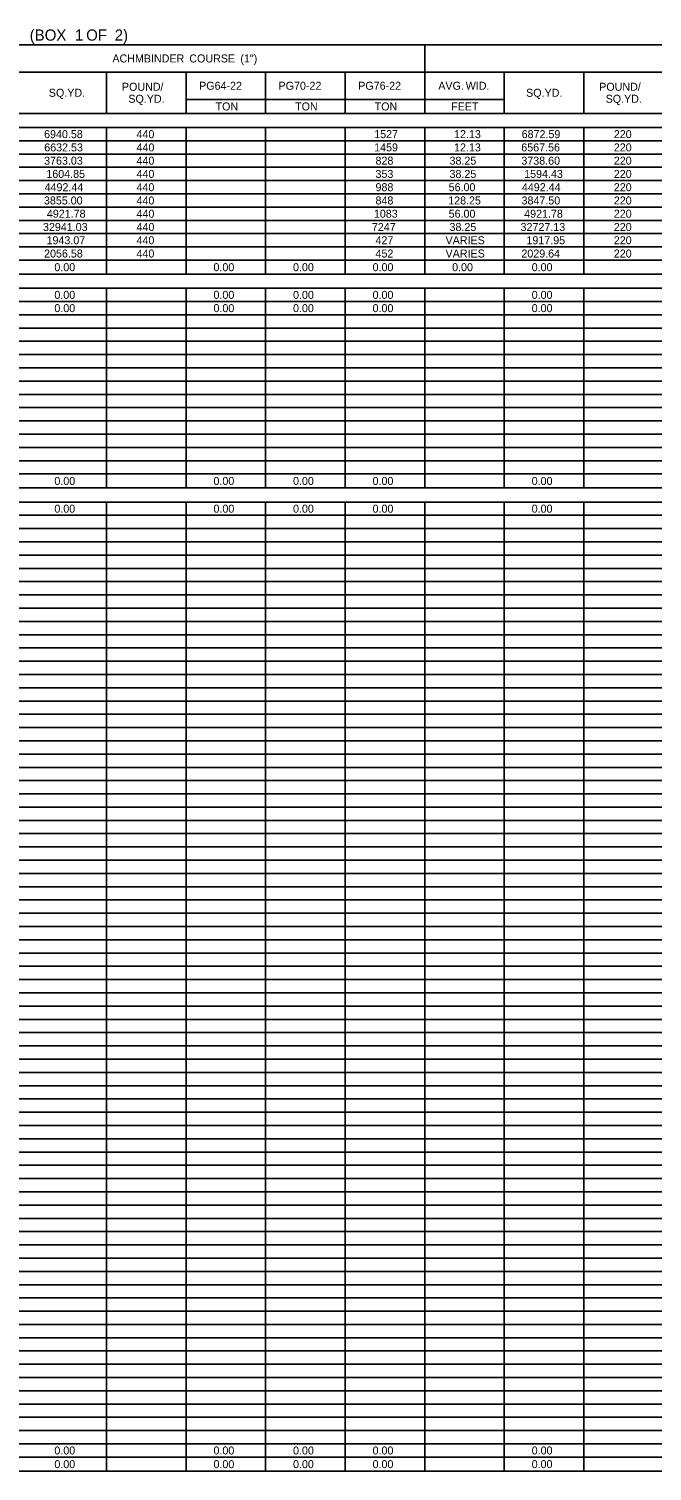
# Model space of a CAD drawing. Extents: x 1226590 to 1228573, y 151304 to 154224.
# Drawn here: x 1227629 to 1228019, y 153323 to 154224 of the extents above; entities that cross this region are included whole.
import ezdxf

# ---------------------------------------------------------------- set-up
doc = ezdxf.new("R2010")
doc.units = 0
doc.layers.add('R_Dimension', color=7, linetype='Continuous')

msp = doc.modelspace()

# ---------------------------------------------------------------- linework, layer by layer
at = {"layer": 'R_Dimension'}
for p, q in [((1226590.27, 154214.43), (1228572.93, 154214.43)), ((1227876.78, 154171.53), (1227876.78, 154214.43)), ((1226981.73, 154197.37), (1228572.93, 154197.37)), ((1227677.88, 154171.53), (1227677.88, 154197.37)), ((1227727.61, 154171.53), (1227727.61, 154197.37)), ((1227777.33, 154171.53), (1227777.33, 154197.37)), ((1227827.06, 154171.53), (1227827.06, 154197.37)), ((1227926.51, 154171.53), (1227926.51, 154197.37)), ((1227976.23, 154171.53), (1227976.23, 154197.37)), ((1227727.61, 154180.3), (1227926.51, 154180.3)), ((1226590.27, 154171.53), (1228572.93, 154171.53)), ((1227628.16, 154171.53), (1227926.51, 154171.53)), ((1227926.51, 154171.53), (1228224.86, 154171.53)), ((1226590.27, 154162.75), (1228572.93, 154162.75)), ((1226590.27, 154154.47), (1228572.93, 154154.47)), ((1227677.88, 154071.1), (1227677.88, 154162.75)), ((1227727.61, 154071.1), (1227727.61, 154162.75)), ((1227777.33, 154071.1), (1227777.33, 154162.75)), ((1227827.06, 154071.1), (1227827.06, 154162.75)), ((1227876.78, 154071.1), (1227876.78, 154162.75)), ((1227926.51, 154071.1), (1227926.51, 154162.75)), ((1227976.23, 154071.1), (1227976.23, 154162.75)), ((1226590.27, 154146.18), (1228572.93, 154146.18)), ((1226590.27, 154137.89), (1228572.93, 154137.89)), ((1226590.27, 154129.6), (1228572.93, 154129.6)), ((1226590.27, 154121.32), (1228572.93, 154121.32)), ((1226590.27, 154113.03), (1228572.93, 154113.03)), ((1226590.27, 154104.74), (1228572.93, 154104.74)), ((1226590.27, 154096.45), (1228572.93, 154096.45)), ((1226590.27, 154088.17), (1228572.93, 154088.17)), ((1226590.27, 154079.88), (1228572.93, 154079.88)), ((1226590.27, 154071.1), (1228572.93, 154071.1)), ((1226590.27, 154062.33), (1228572.93, 154062.33)), ((1227677.88, 153937.53), (1227677.88, 154062.33)), ((1227727.61, 153937.53), (1227727.61, 154062.33)), ((1227777.33, 153937.53), (1227777.33, 154062.33)), ((1227827.06, 153937.53), (1227827.06, 154062.33)), ((1227876.78, 153937.53), (1227876.78, 154062.33)), ((1227926.51, 153937.53), (1227926.51, 154062.33)), ((1227976.23, 153937.53), (1227976.23, 154062.33)), ((1226590.27, 154054.04), (1228572.93, 154054.04)), ((1226590.27, 154045.75), (1228572.93, 154045.75)), ((1226590.27, 154037.47), (1228572.93, 154037.47)), ((1226590.27, 154029.18), (1228572.93, 154029.18)), ((1226590.27, 154020.89), (1228572.93, 154020.89)), ((1226590.27, 154012.6), (1228572.93, 154012.6)), ((1226590.27, 154004.32), (1228572.93, 154004.32)), ((1226590.27, 153996.03), (1228572.93, 153996.03)), ((1226590.27, 153987.74), (1228572.93, 153987.74)), ((1226590.27, 153979.45), (1228572.93, 153979.45)), ((1226590.27, 153971.17), (1228572.93, 153971.17)), ((1226590.27, 153962.88), (1228572.93, 153962.88)), ((1226590.27, 153954.59), (1228572.93, 153954.59)), ((1226590.27, 153946.3), (1228572.93, 153946.3)), ((1226590.27, 153937.53), (1228572.93, 153937.53)), ((1226590.27, 153928.75), (1228572.93, 153928.75)), ((1227677.88, 153323.28), (1227677.88, 153928.75)), ((1227727.61, 153323.28), (1227727.61, 153928.75)), ((1227777.33, 153323.28), (1227777.33, 153928.75)), ((1227827.06, 153323.28), (1227827.06, 153928.75)), ((1227876.78, 153323.28), (1227876.78, 153928.75)), ((1227926.51, 153323.28), (1227926.51, 153928.75)), ((1227976.23, 153323.28), (1227976.23, 153928.75)), ((1226590.27, 153920.47), (1228572.93, 153920.47)), ((1226590.27, 153912.18), (1228572.93, 153912.18)), ((1226590.27, 153903.89), (1228572.93, 153903.89)), ((1226590.27, 153895.6), (1228572.93, 153895.6)), ((1226590.27, 153887.32), (1228572.93, 153887.32)), ((1226590.27, 153879.03), (1228572.93, 153879.03)), ((1226590.27, 153870.74), (1228572.93, 153870.74)), ((1226590.27, 153862.45), (1228572.93, 153862.45)), ((1226590.27, 153854.17), (1228572.93, 153854.17)), ((1226590.27, 153845.88), (1228572.93, 153845.88)), ((1226590.27, 153837.59), (1228572.93, 153837.59)), ((1226590.27, 153829.3), (1228572.93, 153829.3)), ((1226590.27, 153821.02), (1228572.93, 153821.02)), ((1226590.27, 153812.73), (1228572.93, 153812.73)), ((1226590.27, 153804.44), (1228572.93, 153804.44)), ((1226590.27, 153796.15), (1228572.93, 153796.15)), ((1226590.27, 153787.87), (1228572.93, 153787.87)), ((1226590.27, 153779.58), (1228572.93, 153779.58)), ((1226590.27, 153771.29), (1228572.93, 153771.29)), ((1226590.27, 153763), (1228572.93, 153763)), ((1226590.27, 153754.72), (1228572.93, 153754.72)), ((1226590.27, 153746.43), (1228572.93, 153746.43)), ((1226590.27, 153738.14), (1228572.93, 153738.14)), ((1226590.27, 153729.85), (1228572.93, 153729.85)), ((1226590.27, 153721.57), (1228572.93, 153721.57)), ((1226590.27, 153713.28), (1228572.93, 153713.28)), ((1226590.27, 153704.99), (1228572.93, 153704.99)), ((1226590.27, 153696.7), (1228572.93, 153696.7)), ((1226590.27, 153688.42), (1228572.93, 153688.42)), ((1226590.27, 153680.13), (1228572.93, 153680.13)), ((1226590.27, 153671.84), (1228572.93, 153671.84)), ((1226590.27, 153663.55), (1228572.93, 153663.55)), ((1226590.27, 153655.27), (1228572.93, 153655.27)), ((1226590.27, 153646.98), (1228572.93, 153646.98)), ((1226590.27, 153638.69), (1228572.93, 153638.69)), ((1226590.27, 153630.4), (1228572.93, 153630.4)), ((1226590.27, 153622.12), (1228572.93, 153622.12)), ((1226590.27, 153613.83), (1228572.93, 153613.83)), ((1226590.27, 153605.54), (1228572.93, 153605.54)), ((1226590.27, 153597.25), (1228572.93, 153597.25)), ((1226590.27, 153588.97), (1228572.93, 153588.97)), ((1226590.27, 153580.68), (1228572.93, 153580.68)), ((1226590.27, 153572.39), (1228572.93, 153572.39)), ((1226590.27, 153564.1), (1228572.93, 153564.1)), ((1226590.27, 153555.82), (1228572.93, 153555.82)), ((1226590.27, 153547.53), (1228572.93, 153547.53)), ((1226590.27, 153539.24), (1228572.93, 153539.24)), ((1226590.27, 153530.95), (1228572.93, 153530.95)), ((1226590.27, 153522.67), (1228572.93, 153522.67)), ((1226590.27, 153514.38), (1228572.93, 153514.38)), ((1226590.27, 153506.09), (1228572.93, 153506.09)), ((1226590.27, 153497.8), (1228572.93, 153497.8)), ((1226590.27, 153489.52), (1228572.93, 153489.52)), ((1226590.27, 153481.23), (1228572.93, 153481.23)), ((1226590.27, 153472.94), (1228572.93, 153472.94)), ((1226590.27, 153464.65), (1228572.93, 153464.65)), ((1226590.27, 153456.37), (1228572.93, 153456.37)), ((1226590.27, 153448.08), (1228572.93, 153448.08)), ((1226590.27, 153439.79), (1228572.93, 153439.79)), ((1226590.27, 153431.5), (1228572.93, 153431.5)), ((1226590.27, 153423.22), (1228572.93, 153423.22)), ((1226590.27, 153414.93), (1228572.93, 153414.93)), ((1226590.27, 153406.64), (1228572.93, 153406.64)), ((1226590.27, 153398.35), (1228572.93, 153398.35)), ((1226590.27, 153390.07), (1228572.93, 153390.07)), ((1226590.27, 153381.78), (1228572.93, 153381.78)), ((1226590.27, 153373.49), (1228572.93, 153373.49)), ((1226590.27, 153365.2), (1228572.93, 153365.2)), ((1226590.27, 153356.92), (1228572.93, 153356.92)), ((1226590.27, 153348.63), (1228572.93, 153348.63)), ((1226590.27, 153340.34), (1228572.93, 153340.34)), ((1226590.27, 153332.05), (1228572.93, 153332.05)), ((1226590.27, 153323.28), (1228572.93, 153323.28))]:
    msp.add_line(p, q, dxfattribs=at)

# ---------------------------------------------------------------- texts
for s, height, p in [(' (BOX', 7, (1227627.27, 154217.02)), (' 1', 7, (1227655.55, 154217.02)), (' OF', 7, (1227662.55, 154217.02)), (' 2)', 7, (1227680.4, 154217.02)), ('ACHM', 5, (1227681.54, 154203.4)), (' BINDER', 5, (1227699.34, 154203.4)), (' COURSE', 5, (1227727.77, 154203.4)), (' (1")', 5, (1227759.69, 154203.4)), ('POUND', 5, (1227687.49, 154185.7)), (' /', 5, (1227709.73, 154185.7)), ('PG', 5, (1227735.74, 154186.34)), (' 64-22', 5, (1227743.57, 154186.34)), ('PG', 5, (1227785.38, 154186.34)), (' 70-22', 5, (1227793.22, 154186.34)), ('PG', 5, (1227835.19, 154186.34)), (' 76-22', 5, (1227843.02, 154186.34)), ('AVG.', 5, (1227885.25, 154186.34)), (' WID.', 5, (1227900.52, 154186.34)), ('POUND', 5, (1227985.84, 154185.7)), (' /', 5, (1228008.08, 154185.7)), ('SQ.YD.', 5, (1227641.8, 154181.95)), ('SQ.YD.', 5, (1227691.52, 154178.2)), ('SQ.YD.', 5, (1227940.15, 154181.95)), ('SQ.YD.', 5, (1227989.87, 154178.2)), ('TON', 5, (1227746.03, 154173.42)), ('TON', 5, (1227795.76, 154173.42)), ('TON', 5, (1227845.48, 154173.42)), ('FEET', 5, (1227893.28, 154173.42)), ('6940.58', 5, (1227638.85, 154156.11)), ('440', 5, (1227696.62, 154156.11)), ('1527', 5, (1227845.19, 154156.11)), ('12.13', 5, (1227895.11, 154156.11)), ('6872.59', 5, (1227937.37, 154156.11)), ('220', 5, (1227994.97, 154156.11)), ('6632.53', 5, (1227638.93, 154147.82)), ('440', 5, (1227696.62, 154147.82)), ('1459', 5, (1227845.17, 154147.82)), ('12.13', 5, (1227895.11, 154147.82)), ('6567.56', 5, (1227937.14, 154147.82)), ('220', 5, (1227994.97, 154147.82)), ('3763.03', 5, (1227638.85, 154139.54)), ('1604.85', 5, (1227640.26, 154131.25)), ('440', 5, (1227696.62, 154139.54)), ('440', 5, (1227696.62, 154131.25)), ('353', 5, (1227846.01, 154131.25)), ('828', 5, (1227846.01, 154139.54)), ('38.25', 5, (1227892.28, 154139.54)), ('38.25', 5, (1227892.28, 154131.25)), ('3738.60', 5, (1227937.18, 154139.54)), ('1594.43', 5, (1227938.93, 154131.25)), ('220', 5, (1227994.97, 154139.54)), ('220', 5, (1227994.97, 154131.25)), ('4492.44', 5, (1227639.16, 154122.96)), ('440', 5, (1227696.62, 154122.96)), ('988', 5, (1227846.01, 154122.96)), ('56.00', 5, (1227891.74, 154122.96)), ('4492.44', 5, (1227937.51, 154122.96)), ('220', 5, (1227994.97, 154122.96)), ('3855.00', 5, (1227638.75, 154114.67)), ('440', 5, (1227696.62, 154114.67)), ('848', 5, (1227846.01, 154114.67)), ('128.25', 5, (1227891.45, 154114.67)), ('3847.50', 5, (1227937.3, 154114.67)), ('220', 5, (1227994.97, 154114.67)), ('4921.78', 5, (1227640.58, 154106.39)), ('440', 5, (1227696.62, 154106.39)), ('1083', 5, (1227844.99, 154106.39)), ('56.00', 5, (1227891.74, 154106.39)), ('4921.78', 5, (1227938.93, 154106.39)), ('220', 5, (1227994.97, 154106.39)), ('32941.03', 5, (1227638.14, 154098.1)), ('440', 5, (1227696.62, 154098.1)), ('7247', 5, (1227843.77, 154098.1)), ('38.25', 5, (1227892.28, 154098.1)), ('32727.13', 5, (1227936.69, 154098.1)), ('220', 5, (1227994.97, 154098.1)), ('1943.07', 5, (1227640.38, 154089.81)), ('440', 5, (1227696.62, 154089.81)), ('427', 5, (1227846.01, 154089.81)), ('VARIES', 5, (1227889.79, 154089.81)), ('1917.95', 5, (1227940.35, 154089.81)), ('220', 5, (1227994.97, 154089.81)), ('2056.58', 5, (1227638.85, 154081.52)), ('440', 5, (1227696.62, 154081.52)), ('452', 5, (1227846.01, 154081.52)), ('VARIES', 5, (1227889.79, 154081.52)), ('2029.64', 5, (1227937.2, 154081.52)), ('220', 5, (1227994.97, 154081.52)), ('0.00', 5, (1227645.28, 154072.99)), ('0.00', 5, (1227744.73, 154072.99)), ('0.00', 5, (1227794.46, 154072.99)), ('0.00', 5, (1227844.18, 154072.99)), ('0.00', 5, (1227893.91, 154072.99)), ('0.00', 5, (1227943.63, 154072.99)), ('0.00', 5, (1227645.28, 154055.69)), ('0.00', 5, (1227744.73, 154055.69)), ('0.00', 5, (1227794.46, 154055.69)), ('0.00', 5, (1227844.18, 154055.69)), ('0.00', 5, (1227943.63, 154055.69)), ('0.00', 5, (1227645.28, 154047.4)), ('0.00', 5, (1227744.73, 154047.4)), ('0.00', 5, (1227794.46, 154047.4)), ('0.00', 5, (1227844.18, 154047.4)), ('0.00', 5, (1227943.63, 154047.4)), ('0.00', 5, (1227645.28, 153939.42)), ('0.00', 5, (1227744.73, 153939.42)), ('0.00', 5, (1227794.46, 153939.42)), ('0.00', 5, (1227844.18, 153939.42)), ('0.00', 5, (1227943.63, 153939.42)), ('0.00', 5, (1227645.28, 153922.11)), ('0.00', 5, (1227744.73, 153922.11)), ('0.00', 5, (1227794.46, 153922.11)), ('0.00', 5, (1227844.18, 153922.11)), ('0.00', 5, (1227943.63, 153922.11)), ('0.00', 5, (1227645.28, 153333.7)), ('0.00', 5, (1227744.73, 153333.7)), ('0.00', 5, (1227794.46, 153333.7)), ('0.00', 5, (1227844.18, 153333.7)), ('0.00', 5, (1227943.63, 153333.7)), ('0.00', 5, (1227645.28, 153325.17)), ('0.00', 5, (1227744.73, 153325.17)), ('0.00', 5, (1227794.46, 153325.17)), ('0.00', 5, (1227844.18, 153325.17)), ('0.00', 5, (1227943.63, 153325.17))]:
    msp.add_text(s, height=height, dxfattribs=at).set_placement(p)

doc.saveas('drawing.dxf')
